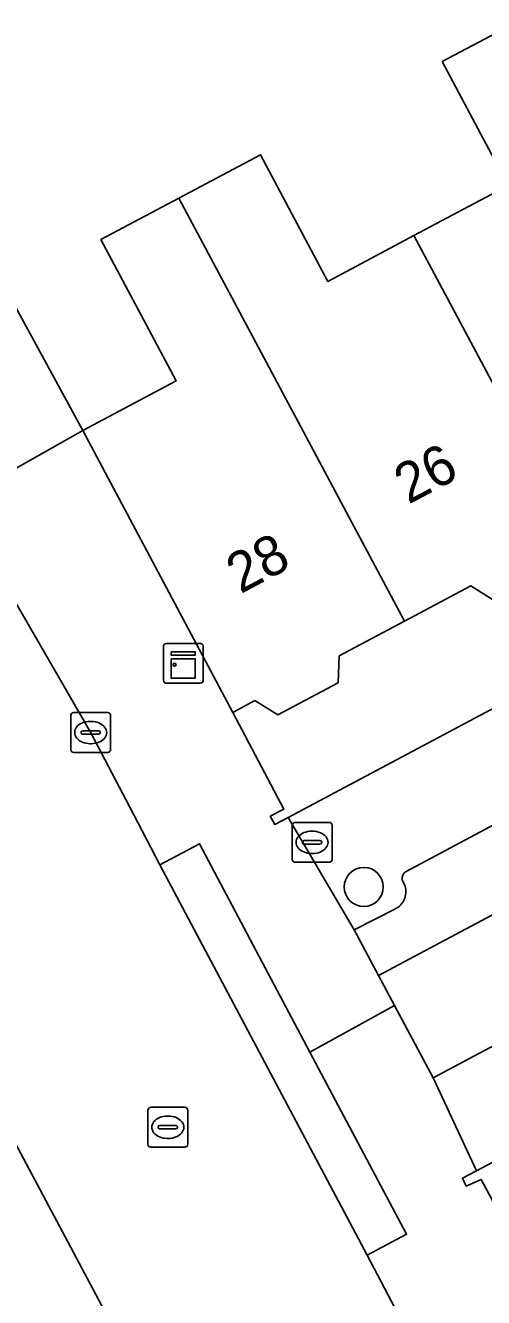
# Model space of a CAD drawing. Extents: x 160304 to 160955, y 383684 to 384161.
# Drawn here: x 160672.07 to 160683.55, y 383909.71 to 383941.59 of the extents above; entities that cross this region are included whole.
import ezdxf

# ---------------------------------------------------------------- set-up
doc = ezdxf.new("R2010")
doc.units = 0
for name, color, linetype in [('IMGEO_Boom', 7, 'Continuous'), ('IMGEO_Brandkraan', 7, 'Continuous'), ('IMGEO_Erf', 7, 'Continuous'), ('IMGEO_Kast', 7, 'Continuous'), ('IMGEO_Kolk', 7, 'Continuous'), ('IMGEO_Pand', 7, 'Continuous'), ('IMGEO_Pand_nummerreeks', 7, 'Continuous'), ('IMGEO_Parkeervlak_open', 7, 'Continuous'), ('IMGEO_Rijbaan_lokaal_open', 7, 'Continuous'), ('IMGEO_Rioolput', 7, 'Continuous'), ('IMGEO_Voetpad_open', 7, 'Continuous')]:
    doc.layers.add(name, color=color, linetype=linetype)

msp = doc.modelspace()

# ---------------------------------------------------------------- linework, layer by layer
at = {"layer": 'IMGEO_Boom'}
msp.add_circle((160680.55, 383919.999), 0.489, dxfattribs=at)
at = {"layer": 'IMGEO_Brandkraan'}
for p, q in [((160678.754, 383920.691), (160678.754, 383921.543)), ((160678.829, 383921.617), (160679.681, 383921.617)), ((160679.755, 383921.543), (160679.755, 383920.691)), ((160679.013, 383921.111), (160679.013, 383921.123)), ((160679.056, 383921.16), (160679.454, 383921.16)), ((160679.242, 383921.397), (160679.267, 383921.397)), ((160679.497, 383921.123), (160679.497, 383921.111)), ((160679.451, 383921.074), (160679.053, 383921.074)), ((160679.265, 383920.837), (160679.24, 383920.837)), ((160679.681, 383920.617), (160678.829, 383920.617))]:
    msp.add_line(p, q, dxfattribs=at)
for points in [[(160678.754, 383920.691), (160678.754, 383921.543)], [(160678.829, 383921.617), (160679.681, 383921.617)], [(160679.755, 383921.543), (160679.755, 383920.691)], [(160679.681, 383920.617), (160678.829, 383920.617)]]:
    msp.add_lwpolyline(points, dxfattribs=at)
for centre, radius, start, end in [((160678.831, 383921.541), 0.0765, 91.552, 178.448), ((160678.831, 383921.541), 0.0765, 91.552, 178.448), ((160679.679, 383921.541), 0.0765, 1.552, 88.448), ((160679.679, 383921.541), 0.0765, 1.552, 88.448), ((160679.053, 383921.12), 0.0403, 85.8775, 175.7526), ((160679.05, 383921.11), 0.0366, 178.938, 274.7102), ((160679.454, 383921.117), 0.043, 264.8664, 352.4533), ((160679.458, 383921.122), 0.0386, 1.7309, 96.639), ((160678.831, 383920.693), 0.0765, 181.552, 268.448), ((160678.831, 383920.693), 0.0765, 181.552, 268.448), ((160679.679, 383920.693), 0.0765, 271.552, 358.448), ((160679.679, 383920.693), 0.0765, 271.552, 358.448)]:
    msp.add_arc(centre, radius, start, end, dxfattribs=at)
for centre, major_axis, ratio, start_param, end_param in [((160679.241, 383921.117), (-0.387, 0.002), 0.722429, 4.712389, 7.853982), ((160679.266, 383921.117), (-0.39, 0.002), 0.717154, 1.570796, 4.712389)]:
    msp.add_ellipse(centre, major_axis=major_axis, ratio=ratio, start_param=start_param, end_param=end_param, dxfattribs=at)
at = {"layer": 'IMGEO_Erf'}
for points in [[(160684.61, 383953.588), (160682.887, 383952.596), (160684.18, 383950.35), (160680.742, 383948.37), (160677.74, 383946.641), (160676.446, 383948.887), (160674.363, 383947.727), (160675.604, 383945.557), (160672.453, 383943.756), (160669.118, 383941.85), (160667.877, 383944.02), (160666.961, 383943.459), (160673.507, 383931.437), (160675.848, 383932.683), (160673.964, 383936.223), (160675.917, 383937.262), (160677.959, 383938.349), (160679.649, 383935.174), (160681.808, 383936.323), (160684.167, 383937.579), (160682.515, 383940.683), (160684.35, 383941.66)], [(160683.802, 383927.189), (160683.231, 383927.546), (160681.571, 383926.662), (160679.93, 383925.788), (160679.907, 383925.117), (160678.392, 383924.311), (160677.819, 383924.669), (160677.267, 383924.375), (160678.544, 383921.946), (160678.205, 383921.771), (160678.321, 383921.561), (160678.654, 383921.738), (160737.631, 383953.138)], [(160731.321, 383938.411), (160683.374, 383912.887), (160683.022, 383912.699), (160683.119, 383912.501), (160683.49, 383912.67), (160684.818, 383910.205)]]:
    msp.add_lwpolyline(points, dxfattribs=at)
at = {"layer": 'IMGEO_Kast'}
for p, q in [((160675.529, 383925.178), (160675.529, 383926.019)), ((160675.529, 383926.019), (160675.529, 383925.178)), ((160675.604, 383926.103), (160676.445, 383926.103)), ((160676.445, 383926.103), (160675.604, 383926.103)), ((160676.529, 383926.028), (160676.529, 383925.187)), ((160676.529, 383925.187), (160676.529, 383926.028)), ((160676.454, 383925.103), (160675.613, 383925.103)), ((160675.613, 383925.103), (160676.454, 383925.103))]:
    msp.add_line(p, q, dxfattribs=at)
for points in [[(160675.724, 383925.893), (160676.324, 383925.893), (160676.324, 383925.808), (160675.724, 383925.808), (160675.724, 383925.893)], [(160675.724, 383925.718), (160676.324, 383925.718), (160676.324, 383925.229), (160675.724, 383925.229), (160675.724, 383925.718)]]:
    msp.add_lwpolyline(points, dxfattribs=at)
msp.add_circle((160675.808, 383925.567), 0.0377, dxfattribs=at)
for centre, start, end in [((160675.607, 383926.025), 92.4484, 184.2845), ((160675.607, 383926.025), 92.4484, 184.2845), ((160676.451, 383926.025), 2.4484, 94.2845), ((160676.451, 383926.025), 2.4484, 94.2845), ((160675.607, 383925.181), 182.4484, 274.2845), ((160675.607, 383925.181), 182.4484, 274.2845), ((160676.451, 383925.181), 272.4484, 4.2845), ((160676.451, 383925.181), 272.4484, 4.2845)]:
    msp.add_arc(centre, 0.0779, start, end, dxfattribs=at)
at = {"layer": 'IMGEO_Kolk'}
for p, q in [((160673.205, 383923.443), (160673.205, 383924.295)), ((160673.28, 383924.369), (160674.132, 383924.369)), ((160674.206, 383924.295), (160674.206, 383923.443)), ((160673.693, 383924.149), (160673.718, 383924.149)), ((160673.464, 383923.863), (160673.464, 383923.875)), ((160673.902, 383923.826), (160673.504, 383923.826)), ((160673.507, 383923.912), (160673.905, 383923.912)), ((160673.948, 383923.875), (160673.948, 383923.863)), ((160674.132, 383923.369), (160673.28, 383923.369)), ((160673.716, 383923.589), (160673.691, 383923.589))]:
    msp.add_line(p, q, dxfattribs=at)
for points in [[(160673.205, 383923.443), (160673.205, 383924.295)], [(160673.28, 383924.369), (160674.132, 383924.369)], [(160674.206, 383924.295), (160674.206, 383923.443)], [(160674.132, 383923.369), (160673.28, 383923.369)]]:
    msp.add_lwpolyline(points, dxfattribs=at)
for centre, radius, start, end in [((160673.282, 383924.293), 0.0765, 91.552, 178.448), ((160673.282, 383924.293), 0.0765, 91.552, 178.448), ((160674.13, 383924.293), 0.0765, 1.552, 88.448), ((160674.13, 383924.293), 0.0765, 1.552, 88.448), ((160673.504, 383923.872), 0.0403, 85.8775, 175.7526), ((160673.501, 383923.862), 0.0366, 178.938, 274.7102), ((160673.905, 383923.869), 0.043, 264.8664, 352.4533), ((160673.909, 383923.874), 0.0386, 1.7309, 96.639), ((160673.282, 383923.445), 0.0765, 181.552, 268.448), ((160673.282, 383923.445), 0.0765, 181.552, 268.448), ((160674.13, 383923.445), 0.0765, 271.552, 358.448), ((160674.13, 383923.445), 0.0765, 271.552, 358.448)]:
    msp.add_arc(centre, radius, start, end, dxfattribs=at)
for centre, major_axis, ratio, start_param, end_param in [((160673.692, 383923.869), (-0.387, 0.002), 0.722429, 4.712389, 7.853982), ((160673.717, 383923.869), (-0.39, 0.002), 0.717154, 1.570796, 4.712389)]:
    msp.add_ellipse(centre, major_axis=major_axis, ratio=ratio, start_param=start_param, end_param=end_param, dxfattribs=at)
at = {"layer": 'IMGEO_Pand'}
for points in [[(160689.965, 383931.129), (160684.35, 383941.66), (160682.515, 383940.683), (160684.167, 383937.579), (160681.808, 383936.323), (160681.998, 383935.966), (160685.76, 383928.912), (160686.2, 383929.147), (160686.799, 383928.773), (160688.301, 383929.573), (160688.324, 383930.255)], [(160681.571, 383926.662), (160683.231, 383927.546), (160683.802, 383927.189), (160685.306, 383927.99), (160685.329, 383928.683), (160685.76, 383928.912), (160681.998, 383935.966), (160681.808, 383936.323), (160679.649, 383935.174), (160677.959, 383938.349), (160675.917, 383937.262)], [(160681.571, 383926.662), (160675.917, 383937.262), (160673.964, 383936.223), (160675.848, 383932.683), (160673.507, 383931.437), (160677.267, 383924.375), (160677.819, 383924.669), (160678.392, 383924.311), (160679.907, 383925.117), (160679.93, 383925.788)]]:
    msp.add_lwpolyline(points, close=True, dxfattribs=at)
at = {"layer": 'IMGEO_Parkeervlak_open'}
msp.add_lwpolyline([(160696.18, 383928.165), (160681.609, 383920.385), (160681.594, 383920.376), (160681.581, 383920.365), (160681.568, 383920.353), (160681.556, 383920.341), (160681.546, 383920.327), (160681.536, 383920.312), (160681.529, 383920.296), (160681.522, 383920.28), (160681.517, 383920.264), (160681.514, 383920.247), (160681.512, 383920.229), (160681.511, 383920.212), (160681.513, 383920.195), (160681.515, 383920.178), (160681.519, 383920.161), (160681.525, 383920.144), (160681.532, 383920.129), (160681.537, 383920.12), (160681.551, 383920.094), (160681.569, 383920.055), (160681.583, 383920.015), (160681.594, 383919.974), (160681.6, 383919.932), (160681.603, 383919.889), (160681.603, 383919.847), (160681.598, 383919.804), (160681.59, 383919.762), (160681.578, 383919.721), (160681.562, 383919.682), (160681.543, 383919.644), (160681.52, 383919.607), (160681.495, 383919.573), (160681.466, 383919.542), (160681.435, 383919.513), (160681.401, 383919.487), (160681.365, 383919.464), (160681.327, 383919.444), (160680.31, 383918.928), (160680.921, 383917.781), (160721.467, 383939.366)], dxfattribs=at)
at = {"layer": 'IMGEO_Rijbaan_lokaal_open'}
msp.add_lwpolyline([(160722.832, 383936.801), (160721.467, 383939.366), (160680.921, 383917.781), (160681.322, 383917.027), (160682.288, 383915.213)], close=True, dxfattribs=at)
for points in [[(160698.422, 383869.109), (160692.989, 383880.566), (160692.837, 383880.981), (160691.168, 383885.513), (160690.888, 383886.273), (160690.85, 383886.385), (160687.649, 383895.859), (160687.584, 383895.992), (160683.512, 383904.948), (160681.85, 383908.464), (160680.633, 383910.769), (160675.442, 383920.557), (160674.779, 383921.821), (160673.701, 383923.877), (160671.738, 383927.276), (160668.265, 383925.27), (160670.852, 383920.79), (160669, 383919.783), (160669.19, 383919.443)], [(160675.723, 383906.234), (160669.847, 383917.258)], [(160669.847, 383917.258), (160675.723, 383906.234)]]:
    msp.add_lwpolyline(points, dxfattribs=at)
at = {"layer": 'IMGEO_Rioolput'}
for p, q in [((160675.139, 383913.55), (160675.139, 383914.402)), ((160675.214, 383914.476), (160676.066, 383914.476)), ((160676.14, 383914.402), (160676.14, 383913.55)), ((160675.627, 383914.256), (160675.652, 383914.256)), ((160675.398, 383913.97), (160675.398, 383913.982)), ((160675.836, 383913.933), (160675.438, 383913.933)), ((160675.441, 383914.019), (160675.839, 383914.019)), ((160675.882, 383913.982), (160675.882, 383913.97)), ((160676.066, 383913.476), (160675.214, 383913.476)), ((160675.65, 383913.696), (160675.625, 383913.696))]:
    msp.add_line(p, q, dxfattribs=at)
for points in [[(160675.139, 383913.55), (160675.139, 383914.402)], [(160675.214, 383914.476), (160676.066, 383914.476)], [(160676.14, 383914.402), (160676.14, 383913.55)], [(160676.066, 383913.476), (160675.214, 383913.476)]]:
    msp.add_lwpolyline(points, dxfattribs=at)
for centre, radius, start, end in [((160675.216, 383914.4), 0.0765, 91.552, 178.448), ((160675.216, 383914.4), 0.0765, 91.552, 178.448), ((160676.064, 383914.4), 0.0765, 1.552, 88.448), ((160676.064, 383914.4), 0.0765, 1.552, 88.448), ((160675.438, 383913.979), 0.0403, 85.8775, 175.7526), ((160675.435, 383913.969), 0.0366, 178.938, 274.7102), ((160675.839, 383913.976), 0.043, 264.8664, 352.4533), ((160675.843, 383913.981), 0.0386, 1.7309, 96.639), ((160675.216, 383913.552), 0.0765, 181.552, 268.448), ((160675.216, 383913.552), 0.0765, 181.552, 268.448), ((160676.064, 383913.552), 0.0765, 271.552, 358.448), ((160676.064, 383913.552), 0.0765, 271.552, 358.448)]:
    msp.add_arc(centre, radius, start, end, dxfattribs=at)
for centre, major_axis, ratio, start_param, end_param in [((160675.626, 383913.976), (-0.387, 0.002), 0.722429, 4.712389, 7.853982), ((160675.651, 383913.976), (-0.39, 0.002), 0.717154, 1.570796, 4.712389)]:
    msp.add_ellipse(centre, major_axis=major_axis, ratio=ratio, start_param=start_param, end_param=end_param, dxfattribs=at)
at = {"layer": 'IMGEO_Voetpad_open'}
for points in [[(160670.424, 383929.702), (160673.507, 383931.437), (160666.961, 383943.459), (160666.156, 383944.39), (160623.685, 383993.483), (160622.845, 383994.454), (160620.767, 383996.856), (160613.663, 384005.068), (160608.608, 384010.922), (160606.643, 384013.229), (160607.2, 384016.252)], [(160737.631, 383953.138), (160678.654, 383921.738), (160680.31, 383918.928), (160681.327, 383919.444), (160681.365, 383919.464), (160681.401, 383919.487), (160681.435, 383919.513), (160681.466, 383919.542), (160681.495, 383919.573), (160681.52, 383919.607), (160681.543, 383919.644), (160681.562, 383919.682), (160681.578, 383919.721), (160681.59, 383919.762), (160681.598, 383919.804), (160681.603, 383919.847), (160681.603, 383919.889), (160681.6, 383919.932), (160681.594, 383919.974), (160681.583, 383920.015), (160681.569, 383920.055), (160681.551, 383920.094), (160681.537, 383920.12), (160681.532, 383920.129), (160681.525, 383920.144), (160681.519, 383920.161), (160681.515, 383920.178), (160681.513, 383920.195), (160681.511, 383920.212), (160681.512, 383920.229), (160681.514, 383920.247), (160681.517, 383920.264), (160681.522, 383920.28), (160681.529, 383920.296), (160681.536, 383920.312), (160681.546, 383920.327), (160681.556, 383920.341), (160681.568, 383920.353), (160681.581, 383920.365), (160681.594, 383920.376), (160681.609, 383920.385), (160696.18, 383928.165)], [(160690.46, 383899.614), (160684.818, 383910.205), (160683.49, 383912.67), (160683.119, 383912.501), (160683.022, 383912.699), (160683.374, 383912.887), (160682.288, 383915.213), (160681.322, 383917.027), (160679.202, 383915.859), (160681.624, 383911.294), (160680.633, 383910.769), (160681.85, 383908.464), (160683.512, 383904.948), (160687.584, 383895.992), (160687.649, 383895.859)]]:
    msp.add_lwpolyline(points, dxfattribs=at)
for points in [[(160731.321, 383938.411), (160731.813, 383938.673), (160732.617, 383939.108), (160733.152, 383939.46), (160733.256, 383939.529), (160743.868, 383945.177), (160746.679, 383946.631), (160764.306, 383956.019), (160763.531, 383958.431), (160746.712, 383949.534), (160747.214, 383948.6), (160742.958, 383946.316), (160742.456, 383947.25), (160725.268, 383938.098), (160722.832, 383936.801), (160682.288, 383915.213), (160683.374, 383912.887)], [(160673.507, 383931.437), (160670.424, 383929.702), (160671.39, 383927.879), (160671.738, 383927.276), (160673.701, 383923.877), (160674.779, 383921.821), (160675.442, 383920.557), (160676.432, 383921.082), (160679.202, 383915.859), (160681.322, 383917.027), (160680.921, 383917.781), (160680.31, 383918.928), (160678.654, 383921.738), (160678.321, 383921.561), (160678.205, 383921.771), (160678.544, 383921.946), (160677.267, 383924.375)], [(160681.624, 383911.294), (160679.202, 383915.859), (160676.432, 383921.082), (160675.442, 383920.557), (160680.633, 383910.769)]]:
    msp.add_lwpolyline(points, close=True, dxfattribs=at)

# ---------------------------------------------------------------- texts
at = {"layer": 'IMGEO_Pand_nummerreeks'}
for s, p in [('26', (160681.668, 383929.577)), ('28', (160677.46, 383927.333))]:
    msp.add_text(s, height=1, rotation=28.0578, dxfattribs=at).set_placement(p)

doc.saveas('drawing.dxf')
